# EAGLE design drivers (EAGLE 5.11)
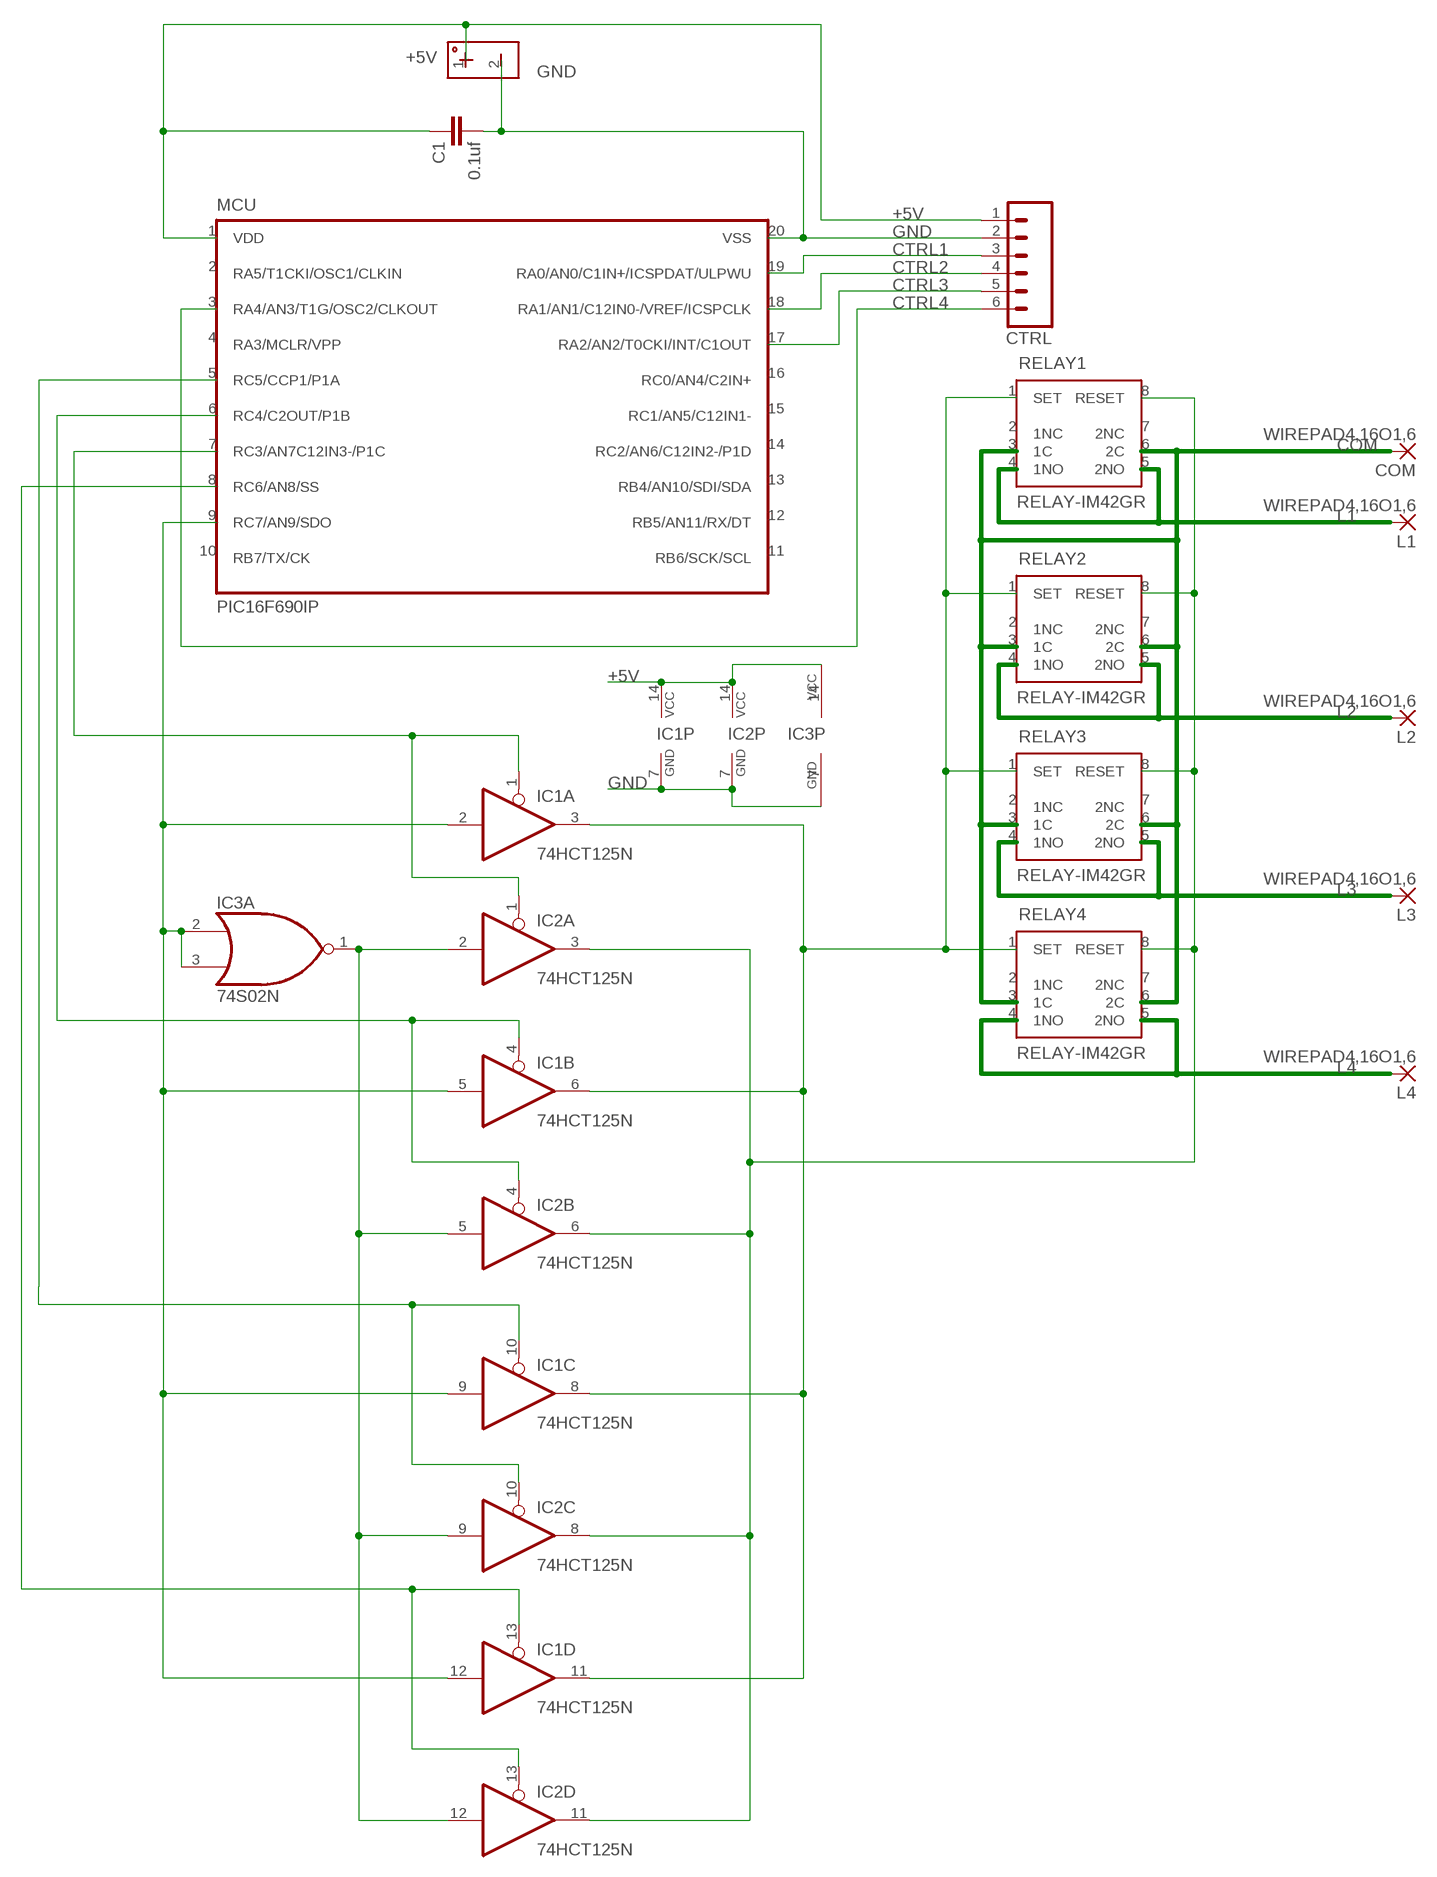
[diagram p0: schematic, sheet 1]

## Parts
+5V  HEADER-POWER  [HEADER-POWER-PTH]
C1  0.1uf  C-EU025-025X050  [C025-025X050]
COM  WIREPAD4,16O1,6  [4,16O1,6]
CTRL  M06POLAR  [MOLEX-1X6]
IC1  74HCT125N  [DIL14]
IC2  74HCT125N  [DIL14]
IC3  74S02N  [DIL14]
L1  WIREPAD4,16O1,6  [4,16O1,6]
L2  WIREPAD4,16O1,6  [4,16O1,6]
L3  WIREPAD4,16O1,6  [4,16O1,6]
L4  WIREPAD4,16O1,6  [4,16O1,6]
MCU  PIC16F690IP  [DIL20]
RELAY1  RELAY-IM42GR  [RELAY-IM42GR]
RELAY2  RELAY-IM42GR  [RELAY-IM42GR]
RELAY3  RELAY-IM42GR  [RELAY-IM42GR]
RELAY4  RELAY-IM42GR  [RELAY-IM42GR]

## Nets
+5V: +5V.1 C1.1 CTRL.1 IC1.14(P:VCC) IC2.14(P:VCC) IC3.14(P:VCC) MCU.1(VDD)
COM: COM.1(P) RELAY1.3(1C) RELAY1.6(2C) RELAY2.3(1C) RELAY2.6(2C) RELAY3.3(1C) RELAY3.6(2C) RELAY4.3(1C) RELAY4.6(2C)
CTRL1: CTRL.3 MCU.19(RA0/AN0/C1IN+/ICSPDAT/ULPWU)
CTRL2: CTRL.4 MCU.18(RA1/AN1/C12IN0-/VREF/ICSPCLK)
CTRL3: CTRL.5 MCU.17(RA2/AN2/T0CKI/INT/C1OUT)
CTRL4: CTRL.6 MCU.3(RA4/AN3/T1G/OSC2/CLKOUT)
GND: +5V.2 C1.2 CTRL.2 IC1.7(P:GND) IC2.7(P:GND) IC3.7(P:GND) MCU.20(VSS)
L1: L1.1(P) RELAY1.4(1NO) RELAY1.5(2NO)
L2: L2.1(P) RELAY2.4(1NO) RELAY2.5(2NO)
L3: L3.1(P) RELAY3.4(1NO) RELAY3.5(2NO)
L4: L4.1(P) RELAY4.4(1NO) RELAY4.5(2NO)
N$1: IC1.3(A:O) IC1.6(B:O) IC1.8(C:O) IC1.11(D:O) RELAY1.1(SET) RELAY2.1(SET) RELAY3.1(SET) RELAY4.1(SET)
N$2: IC2.3(A:O) IC2.6(B:O) IC2.8(C:O) IC2.11(D:O) RELAY1.8(RESET) RELAY2.8(RESET) RELAY3.8(RESET) RELAY4.8(RESET)
N$3: IC1.1(A:OE) IC2.1(A:OE) MCU.7(RC3/AN7C12IN3-/P1C)
N$8: IC1.4(B:OE) IC2.4(B:OE) MCU.6(RC4/C2OUT/P1B)
N$9: IC1.13(D:OE) IC2.13(D:OE) MCU.8(RC6/AN8/SS)
N$11: IC2.2(A:I) IC2.5(B:I) IC2.9(C:I) IC2.12(D:I) IC3.1(A:O)
N$12: IC1.10(C:OE) IC2.10(C:OE) MCU.5(RC5/CCP1/P1A)
N$14: IC1.2(A:I) IC1.5(B:I) IC1.9(C:I) IC1.12(D:I) IC3.2(A:I0) IC3.3(A:I1) MCU.9(RC7/AN9/SDO)
Unconnected: IC3.4(B:O) IC3.5(B:I0) IC3.6(B:I1) IC3.8(C:I0) IC3.9(C:I1) IC3.10(C:O) IC3.11(D:I0) IC3.12(D:I1) IC3.13(D:O) MCU.2(RA5/T1CKI/OSC1/CLKIN) MCU.4(RA3/MCLR/VPP) MCU.10(RB7/TX/CK) MCU.11(RB6/SCK/SCL) MCU.12(RB5/AN11/RX/DT) MCU.13(RB4/AN10/SDI/SDA) MCU.14(RC2/AN6/C12IN2-/P1D) MCU.15(RC1/AN5/C12IN1-) MCU.16(RC0/AN4/C2IN+) RELAY1.2(1NC) RELAY1.7(2NC) RELAY2.2(1NC) RELAY2.7(2NC) RELAY3.2(1NC) RELAY3.7(2NC) RELAY4.2(1NC) RELAY4.7(2NC)

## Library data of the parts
+5V = trl:HEADER-POWER
C1 = rcl:C-EU: CAPACITOR, European symbol
COM L1-L4 = wirepad:WIREPAD: Wire PAD connect wire on PCB
CTRL = SparkFun2011-02-20:M06: Header 6 Standard 6-pin 0.1" header. Use with straight break away headers (SKU : PRT-00116), right angle break away headers (PRT-00553), swiss pins (PRT-00743), machine pins (PRT-00117), and female headers (PRT-00115). Molex polarized connector foot print use with SKU : PRT-08094 with associated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
IC1 IC2 = 74xx-eu:74*125: Quad bus BUFFER, 3-state
IC3 = 74xx-us:74*02: Quad 2-input NOR gate
MCU = trl:PIC16F690*: MICROCONTROLLER PIC16F690 18 I/O One 16-bit timer Two 8-bit timer Two comparators Precision internal oscillator-software selectable 8 MHz - 32 KHz SSP w/ I2C Compatible Address mask option EUSART LIN 2.0 Compatible ECCP+ w/ PWM Steering 12 A/D Channels ULPW Enhanced Low Power Timer 1 Timer 1 Gate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
RELAY1-RELAY4 = trl:RELAY-IM42GR

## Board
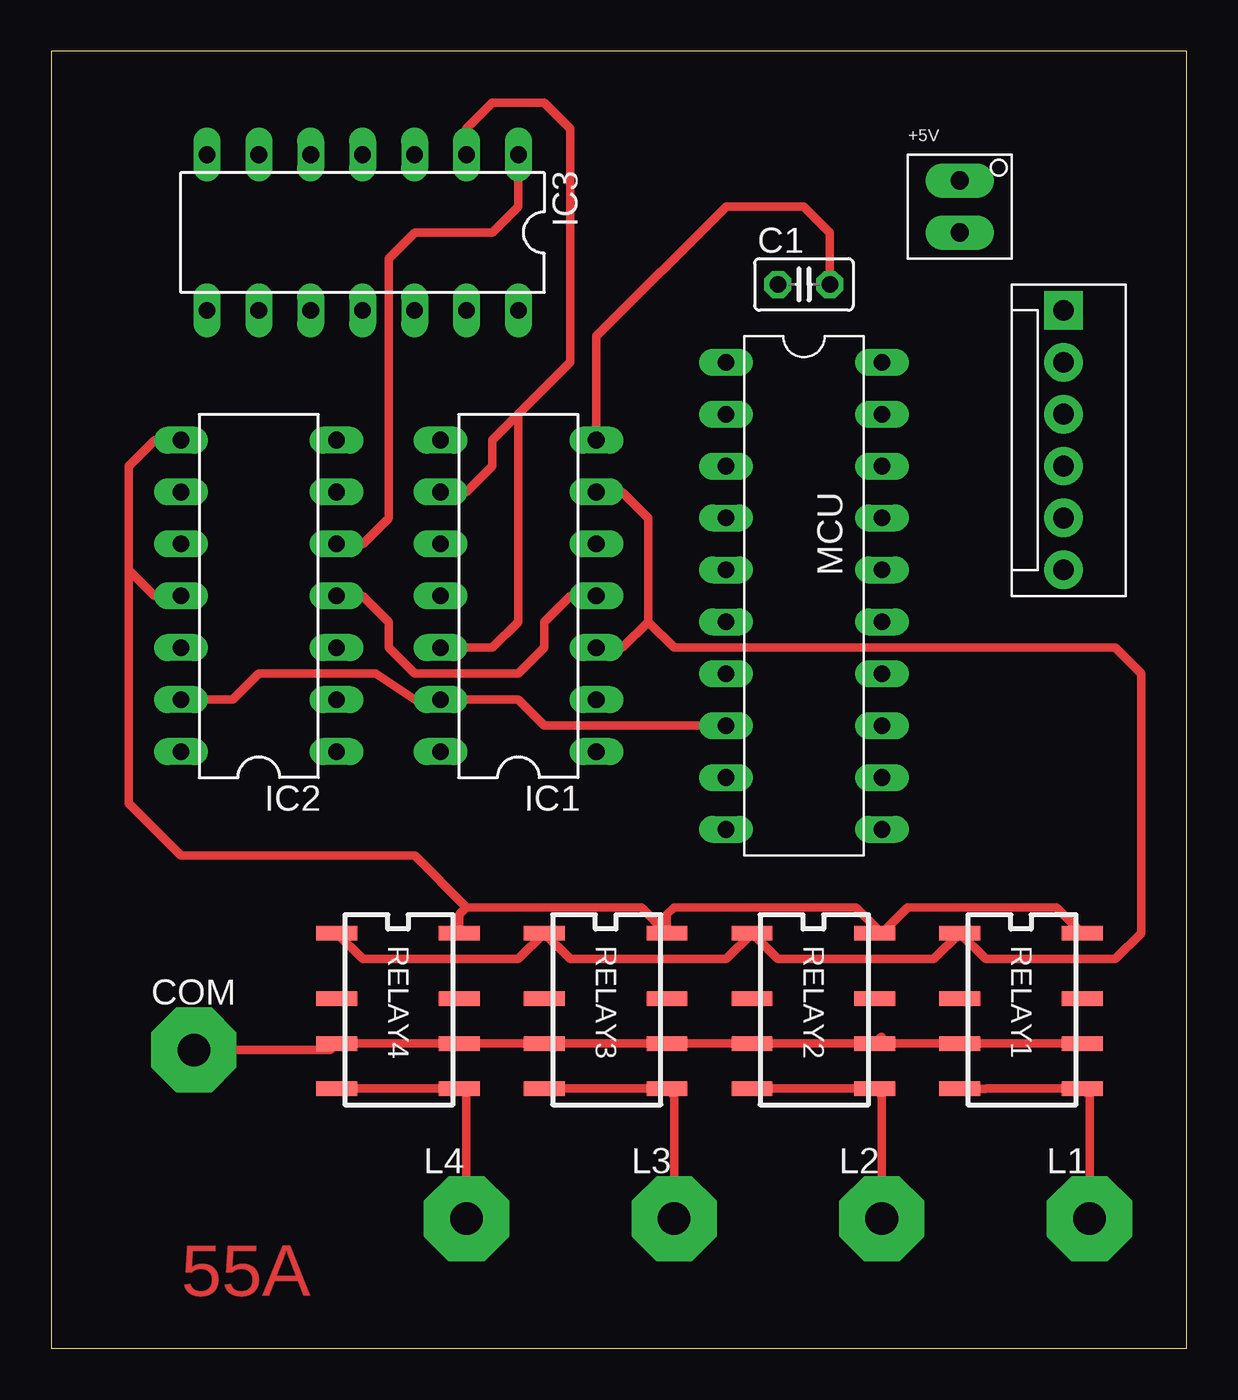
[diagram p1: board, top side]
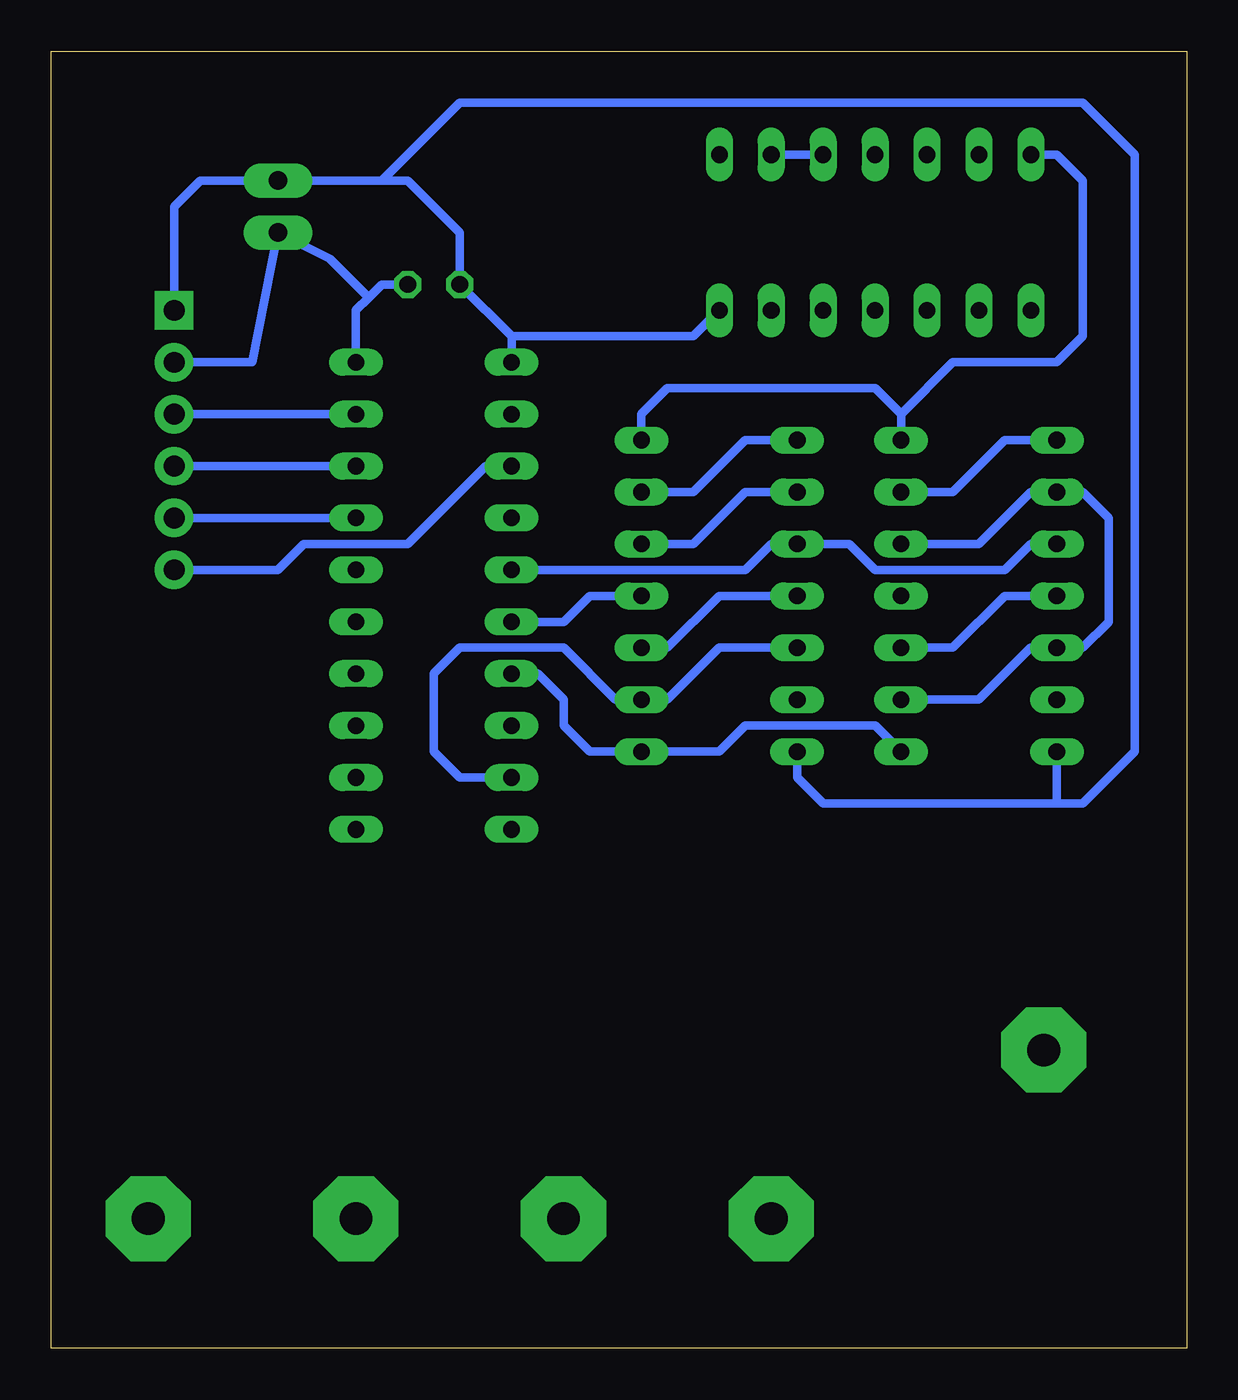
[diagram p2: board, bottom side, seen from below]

Size 55.55 x 63.49 mm. Coordinates in mm from the lower left corner, seen from the top.
Outline: 0,0 55.55,0 55.55,63.49 0,63.49 0,0
Copper layers (1*16): Top 0.035mm / dielectric 1.5mm / Bottom 0.035mm
Design rules "default": minimum track width 10mil, minimum drill 0.6mm, track to track 8mil, track to pad 8mil, pad to pad 8mil, via to via 8mil, smd to smd 8mil, copper to edge 40mil, drill to drill 8mil, minimum pad ring 10mil, minimum via ring 8mil, stop-mask expansion 4mil, vias tented up to drill 0mil, thermal gap 10mil

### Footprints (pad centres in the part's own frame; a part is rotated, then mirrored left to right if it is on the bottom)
HEADER-POWER-PTH = drill 0.9 pad 1.676 long: 1 0,1.27; 2 0,-1.27
C025-025X050 = drill 0.813 octagon: 1 -1.27,0; 2 1.27,0
4,16O1,6 = drill 1.6 pad 4.166 octagon: 1 0,0
MOLEX-1X6 = drill 1.016 pad 1.88 square: 1 0,0 | drill 1.016 pad 1.88 round: 2 2.54,0; 3 5.08,0; 4 7.62,0; 5 10.16,0; 6 12.7,0
DIL14 = drill 0.813 long: 1 -7.62,-3.81; 2 -5.08,-3.81; 3 -2.54,-3.81; 4 0,-3.81; 5 2.54,-3.81; 6 5.08,-3.81; 7 7.62,-3.81; 8 7.62,3.81; 9 5.08,3.81; 10 2.54,3.81; 11 0,3.81; 12 -2.54,3.81; 13 -5.08,3.81; 14 -7.62,3.81
DIL20 = drill 0.813 long: 1 -11.43,-3.81; 2 -8.89,-3.81; 3 -6.35,-3.81; 4 -3.81,-3.81; 5 -1.27,-3.81; 6 1.27,-3.81; 7 3.81,-3.81; 8 6.35,-3.81; 9 8.89,-3.81; 10 11.43,-3.81; 11 11.43,3.81; 12 8.89,3.81; 13 6.35,3.81; 14 3.81,3.81; 15 1.27,3.81; 16 -1.27,3.81; 17 -3.81,3.81; 18 -6.35,3.81; 19 -8.89,3.81; 20 -11.43,3.81
RELAY-IM42GR = smd 2 x 0.7: 1 0,0; 2 0,-3.2; 3 0,-5.4; 4 0,-7.6; 5 6,-7.6; 6 6,-5.4; 7 6,-3.2; 8 6,0

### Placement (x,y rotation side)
+5V  44.45,55.88 0 top
C1  36.83,52.07 0 top
COM  6.99,14.61 0 top
CTRL  49.53,50.8 270 top
IC1  22.86,36.83 90 top
IC2  10.16,36.83 90 top
IC3  15.24,54.61 180 top
L1  50.8,6.35 0 top
L2  40.64,6.35 0 top
L3  30.48,6.35 0 top
L4  20.32,6.35 0 top
MCU  36.83,36.83 270 top
RELAY1  44.45,20.32 0 top
RELAY2  34.29,20.32 0 top
RELAY3  24.13,20.32 0 top
RELAY4  13.97,20.32 0 top

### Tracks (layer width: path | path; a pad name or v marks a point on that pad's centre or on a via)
+5V
  Bottom 0.406: 39.37,57.15 38.1,57.15 35.56,54.61 C1.1 33.02,49.53 | IC1.14 19.05,27.94 17.78,26.67 6.35,26.67 | 6.35,26.67 5.08,26.67 2.54,29.21 2.54,58.42 5.08,60.96 35.56,60.96 39.37,57.15 | 6.35,26.67 IC2.14 | 33.02,49.53 MCU.1 | 33.02,49.53 24.13,49.53 IC3.14 | 39.37,57.15 +5V.1 48.26,57.15 49.53,55.88 CTRL.1
COM
  Top 0.406: COM.1 13.66,14.61 RELAY4.3 RELAY4.6 RELAY3.3 RELAY3.6 RELAY2.3 RELAY2.6 | RELAY2.6 40.32,14.92 40.64,15.24 40.61,15.24 RELAY2.6 | RELAY2.6 RELAY1.3 RELAY1.6
CTRL1
  Bottom 0.406: MCU.19 CTRL.3
CTRL2
  Bottom 0.406: MCU.18 CTRL.4
CTRL3
  Bottom 0.406: MCU.17 CTRL.5
CTRL4
  Bottom 0.406: CTRL.6 44.45,38.1 43.18,39.37 38.1,39.37 34.29,43.18 MCU.3
GND
  Top 0.406: IC1.7 26.67,49.53 33.02,55.88 36.83,55.88 38.1,54.61 C1.2
  Bottom 0.406: MCU.20 40.64,50.8 40,51.44 | 40,51.44 39.37,52.07 C1.2 | 40,51.44 41.91,53.34 +5V.2 45.72,48.26 CTRL.2 | 13.97,45.72 11.43,48.26 6.35,48.26 5.08,49.53 5.08,57.15 6.35,58.42 IC3.7 | 13.97,45.72 IC2.7 | 13.97,45.72 15.24,46.99 25.4,46.99 26.67,45.72 IC1.7
L1
  Top 0.406: RELAY1.4 44.47,12.7 45.72,12.7 45.74,12.72 RELAY1.5 50.8,12.37 L1.1
L2
  Top 0.406: RELAY2.4 34.29,12.7 34.31,12.72 RELAY2.5 40.64,12.37 L2.1
L3
  Top 0.406: RELAY3.4 RELAY3.5 30.48,12.37 L3.1
L4
  Top 0.406: 19.05,12.72 RELAY4.4 | 19.05,12.72 RELAY4.5 | L4.1 20.32,12.7 19.07,12.7 19.05,12.72
N$1
  Top 0.406: RELAY4.1 15.24,19.05 22.86,19.05 RELAY3.1 25.4,19.05 33.02,19.05 RELAY2.1 35.56,19.05 43.18,19.05 RELAY1.1 45.72,19.05 52.07,19.05 53.34,20.32 53.34,33.02 52.07,34.29 30.48,34.29 29.21,35.56 | IC1.6 27.94,41.91 29.21,40.64 29.21,35.56 | 29.21,35.56 27.94,34.29 IC1.3
  Bottom 0.406: IC1.8 21.59,44.45 24.13,41.91 IC1.6 | IC1.3 25.4,34.29 22.86,36.83 IC1.11
N$2
  Top 0.406: RELAY4.8 19.97,21.24 20.32,21.59 | 20.32,21.59 28.86,21.59 RELAY3.8 30.13,21.24 30.48,21.59 39.37,21.59 40.64,20.32 | 40.64,20.32 RELAY2.8 | 40.64,20.32 41.91,21.59 49.18,21.59 RELAY1.8 | IC2.11 5.08,36.83 3.81,38.1 | 3.81,38.1 3.81,43.18 5.08,44.45 IC2.8 | 20.32,21.59 17.78,24.13 6.35,24.13 3.81,26.67 3.81,38.1
  Bottom 0.406: IC2.8 8.89,44.45 11.43,41.91 IC2.6 | IC2.3 11.43,34.29 8.89,36.83 IC2.11
N$3
  Bottom 0.406: IC2.1 15.24,30.48 21.59,30.48 22.86,29.21 IC1.1 29.21,29.21 30.48,30.48 30.48,31.75 31.75,33.02 MCU.7
N$8
  Top 0.406: IC2.4 15.24,36.83 16.51,35.56 16.51,34.29 17.78,33.02 22.86,33.02 24.13,34.29 24.13,35.56 25.4,36.83 IC1.4
  Bottom 0.406: MCU.6 30.48,35.56 29.21,36.83 IC1.4
N$9
  Top 0.406: IC2.13 8.89,31.75 10.16,33.02 15.88,33.02 17.78,31.75 IC1.13 22.86,31.75 24.13,30.48 MCU.8
N$11
  Top 0.406: IC2.5 15.24,39.37 16.51,40.64 16.51,53.34 17.78,54.61 21.59,54.61 22.86,55.88 IC3.1
  Bottom 0.406: IC2.5 10.16,39.37 7.62,41.91 IC2.9 5.08,41.91 3.81,40.64 3.81,35.56 5.08,34.29 IC2.12 7.62,34.29 10.16,31.75 IC2.2
N$12
  Bottom 0.406: MCU.5 21.59,38.1 20.32,39.37 IC1.10 16.51,39.37 15.24,38.1 8.89,38.1 7.62,39.37 IC2.10
N$14
  Top 0.406: IC3.2 20.32,59.69 21.59,60.96 24.13,60.96 25.4,59.69 25.4,48.26 22.86,45.72 | 22.86,45.72 21.59,44.45 21.59,43.18 20.32,41.91 IC1.9 | IC1.12 21.59,34.29 22.86,35.56 22.86,45.72
  Bottom 0.406: IC3.2 IC3.3 | IC1.5 24.13,39.37 21.59,41.91 IC1.9 | MCU.9 35.56,27.94 36.83,29.21 36.83,33.02 35.56,34.29 30.48,34.29 27.94,31.75 IC1.2 25.4,31.75 22.86,34.29 IC1.12

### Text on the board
Top: 55A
